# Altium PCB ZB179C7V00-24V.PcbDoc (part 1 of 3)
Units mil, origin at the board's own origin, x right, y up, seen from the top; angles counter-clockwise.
Board outline 6000 x 4000 mil, 2 copper layers (Top Layer, Bottom Layer); 365 components, 297 nets, 1012 pads, 642 vias.
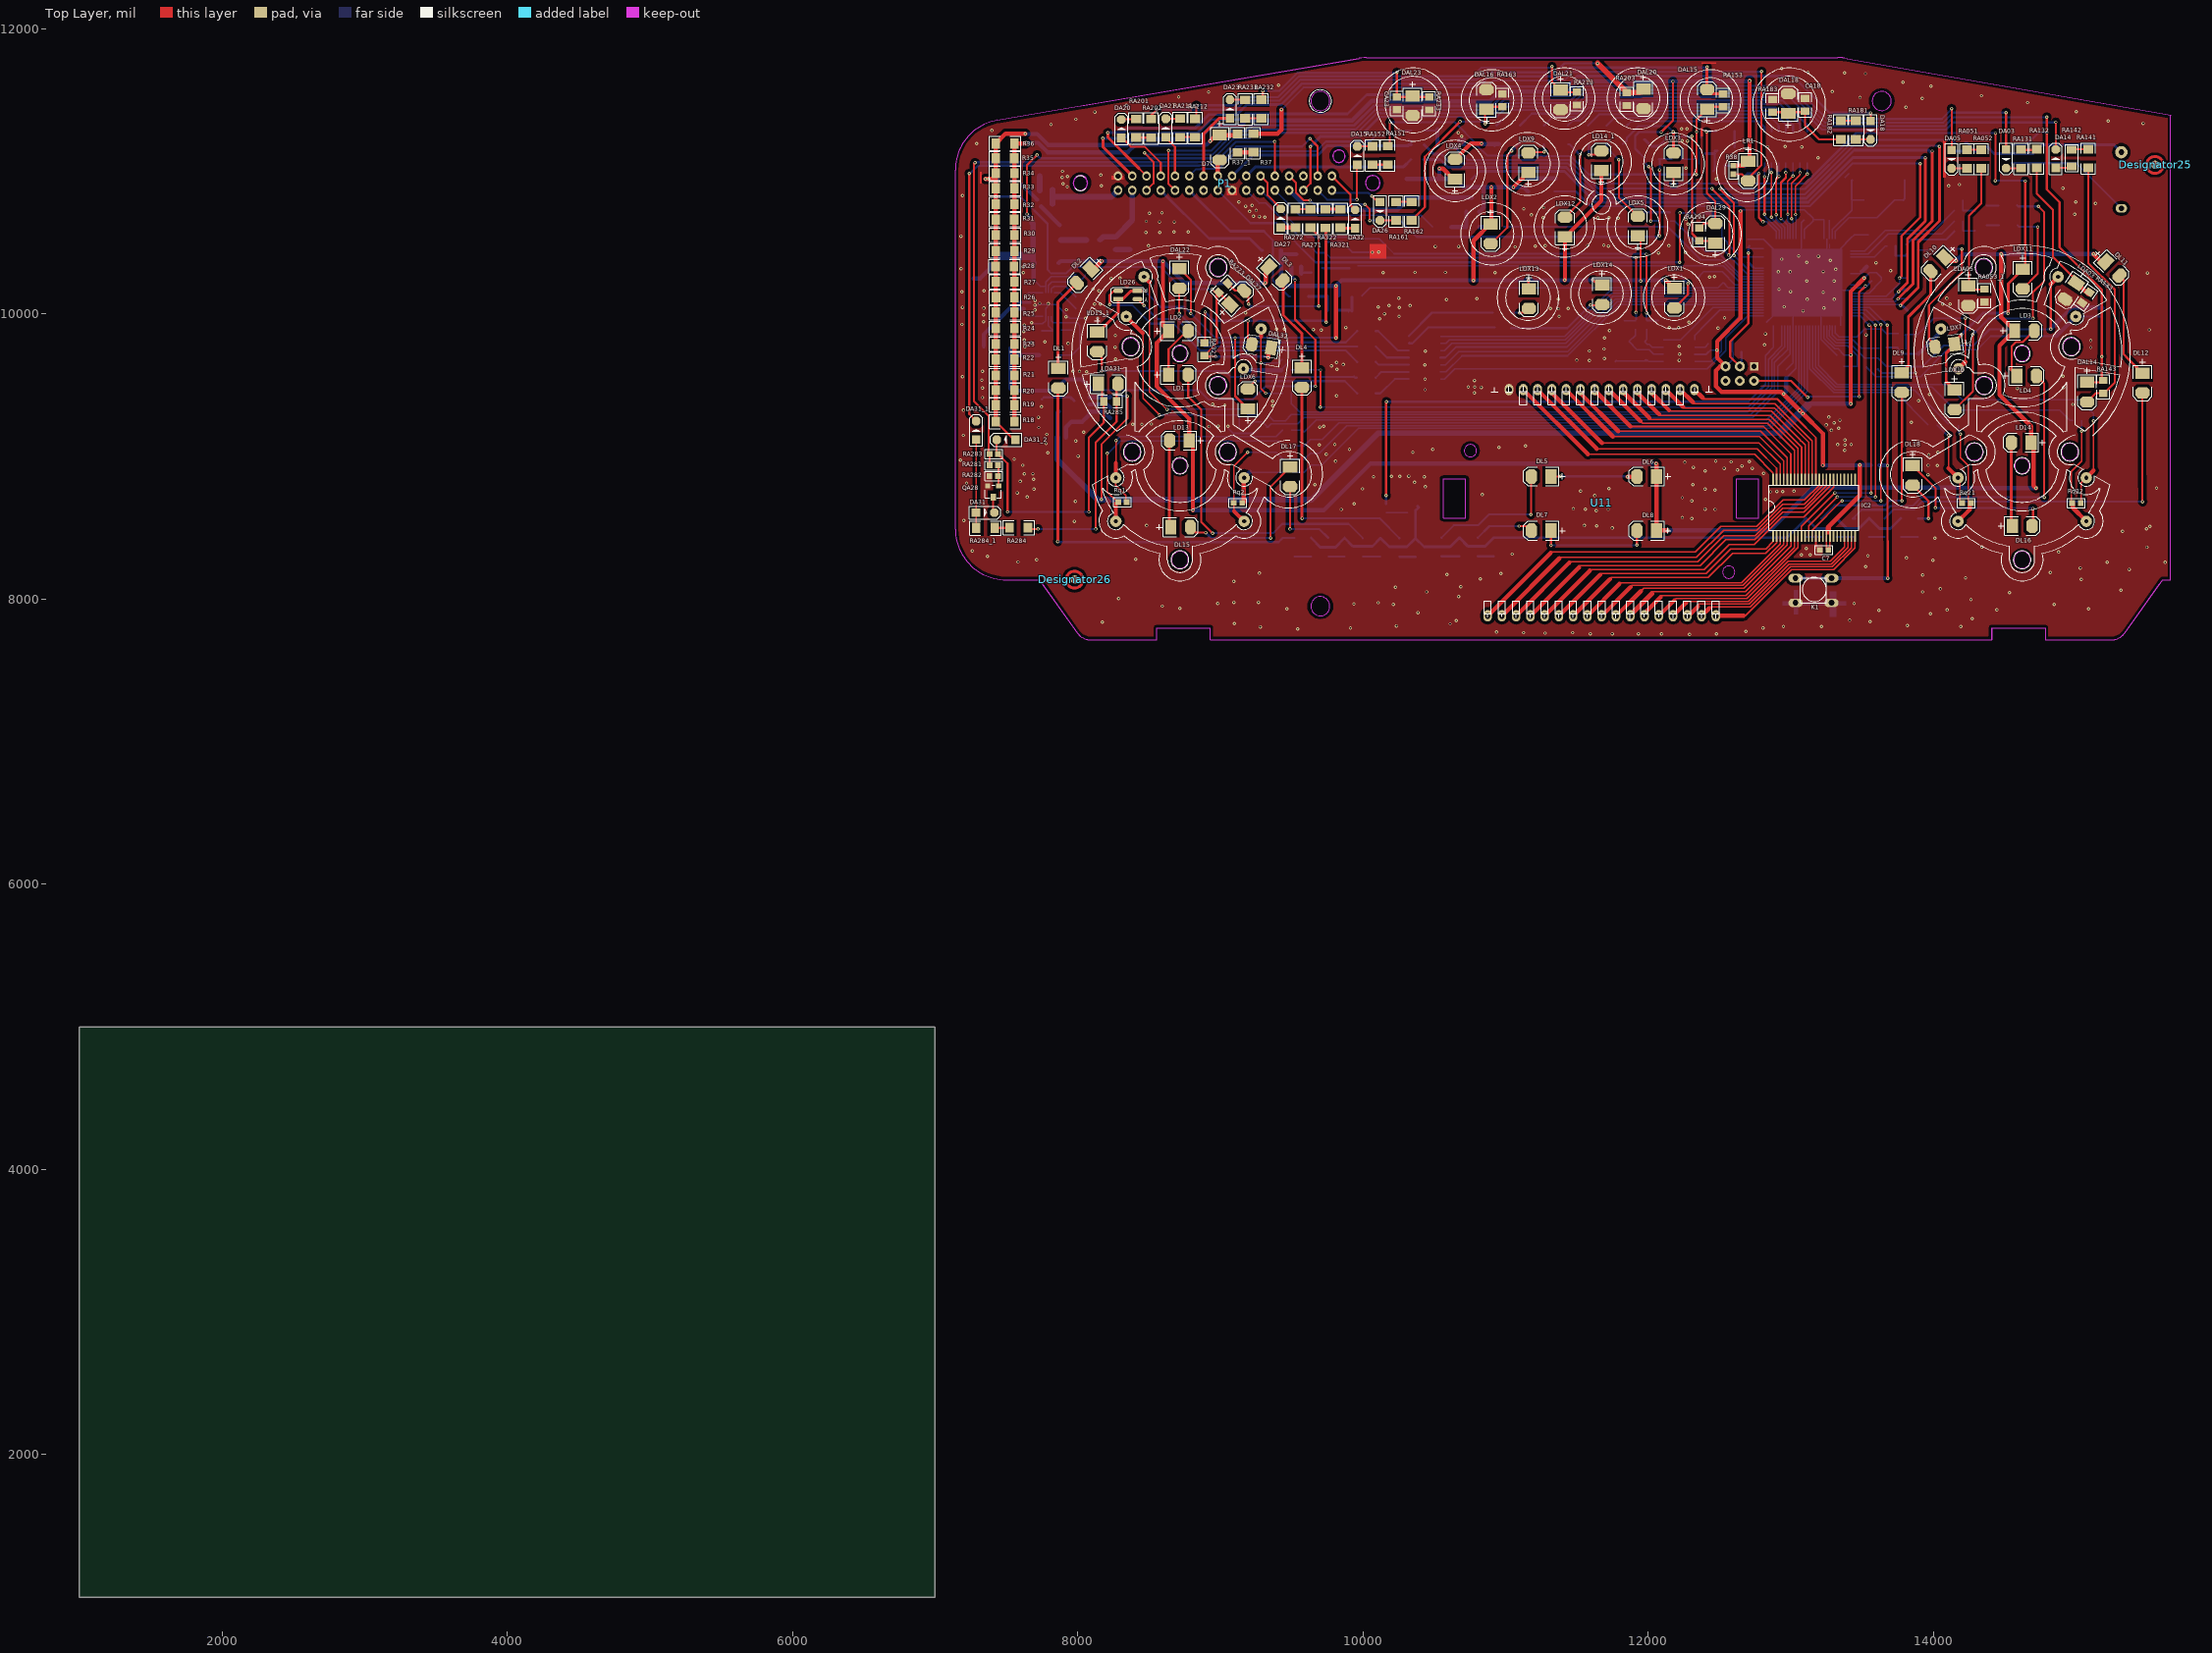
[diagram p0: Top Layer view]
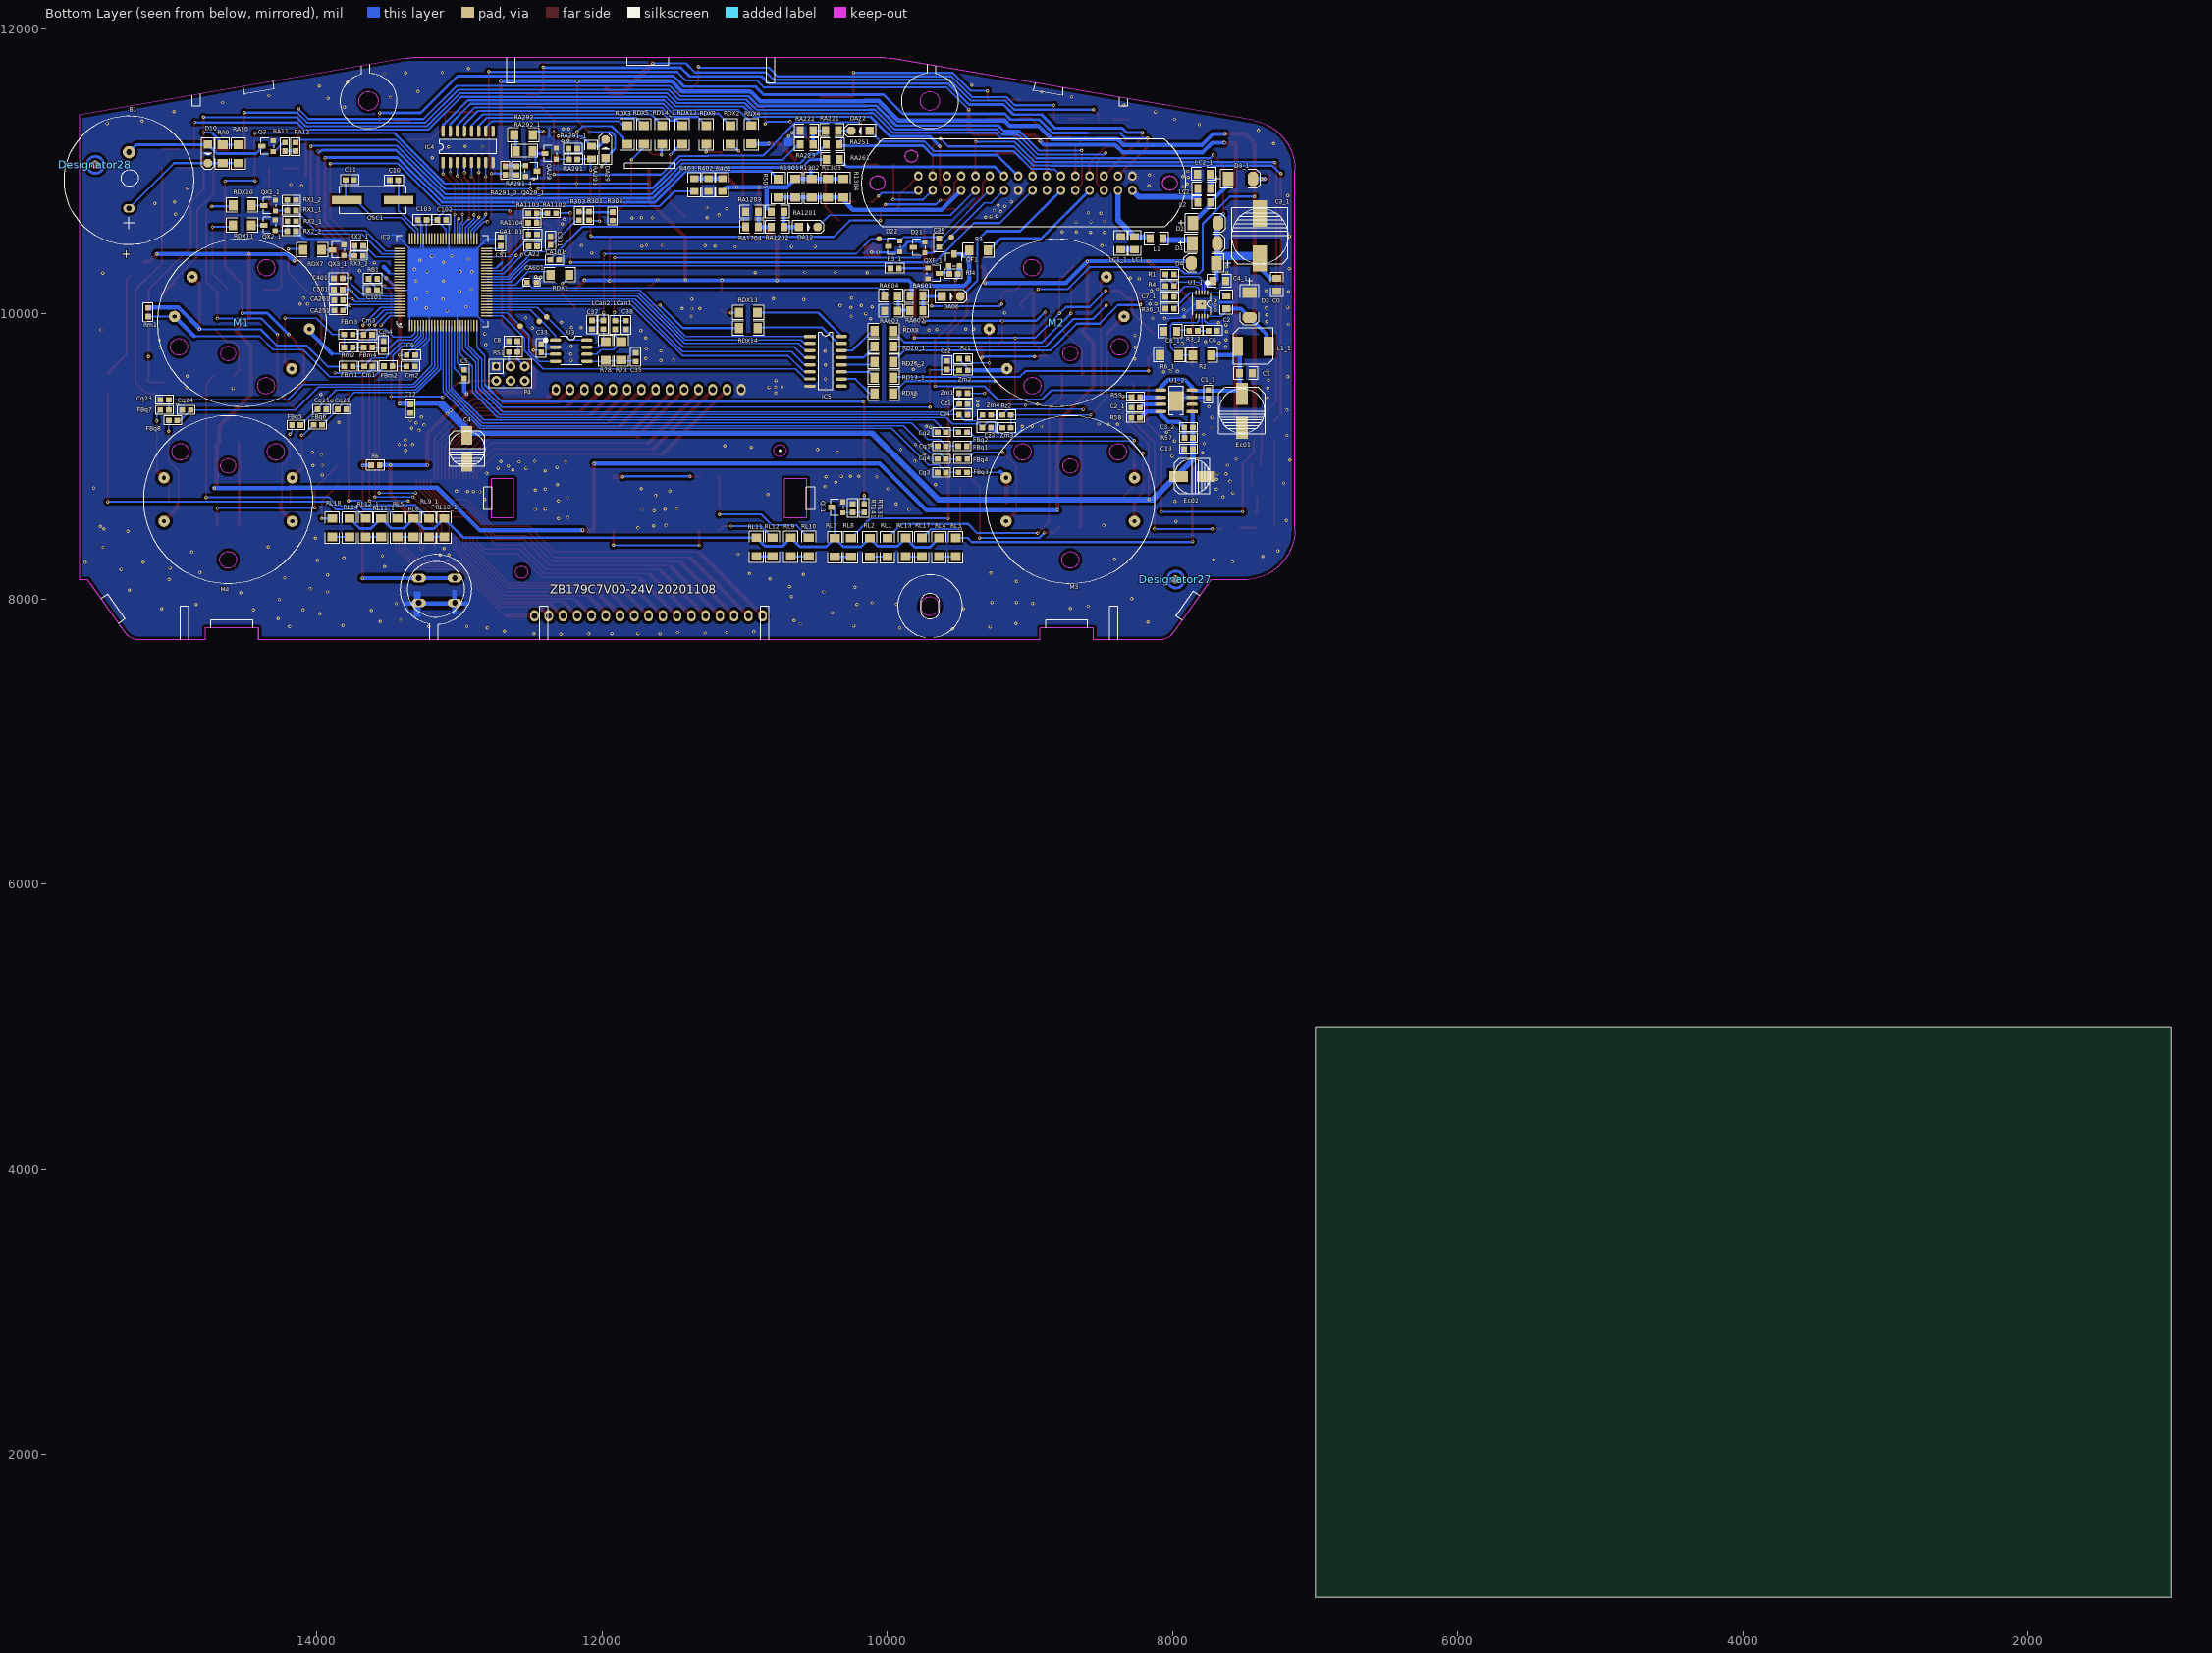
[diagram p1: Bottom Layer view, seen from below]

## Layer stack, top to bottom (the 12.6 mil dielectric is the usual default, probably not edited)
Top Layer: signal copper 1.4
Dielectric: core 12.6, FR-4, Dk 4.8
Bottom Layer: signal copper 1.4

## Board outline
1000,1000 7000,1000 7000,5000 1000,5000

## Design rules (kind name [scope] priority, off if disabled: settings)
Clearance Clearance_1 [All] p1 off: gap=20
Clearance [All] p2: gap=9.5
ComponentClearance [All] p1 off: gap=10 collisioncheckmode=3 verticalgap=10 showdistances=FALSE
FabricationTestPointUsage TestPointUsage [All] p1: valid=0 allowmultiple=FALSE
FabricationTestpoint Testpoint [All] p1: side=3 testpointundercomponent=TRUE minsize=40 maxsize=100 preferedsize=60 minholesize=0 maxholesize=40 preferedholesize=32 testpointgrid=1 allowsidetop=TRUE allowsidebottom=TRUE usegrid=TRUE gridtolerance=0.01
HoleToHoleClearance [All] p1 off: gap=10 allowstackedmicrovias=TRUE
MinimumSolderMaskSliver [All] p1 off: minsoldermaskwidth=10
PlaneConnect [All] p1: planeconnectstyle=Direct reliefexpansion=20 reliefentries=4 reliefconductorwidth=10 reliefairgap=10
PolygonConnect [All] p1: connectstyle=Direct reliefconductorwidth=10 reliefentries=4 polygonreliefangle="90 Angle"
RoutingVias [All] p1: holewidth=11.81 width=23.62 viastyle="Through Hole" minholewidth=11.81 minwidth=23.62 maxholewidth=11.81 maxwidth=23.62
SilkToSilkClearance [All] p1 off: silktosilkclearance=10
SilkscreenOverComponentPads [All] p1 off: minsilkscreentomaskgap=10
SolderMaskExpansion [All] p1: expansion=4
Width [All] p1: maxlimit=100 minlimit=9.8 preferedwidth=10 minimp=50.000000 maximp=50.000000 favimp=50.000000
20 further rules are at their usual default settings.

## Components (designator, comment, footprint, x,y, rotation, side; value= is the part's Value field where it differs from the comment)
B1 "BMT2512H12-04 LF" AZ-2320E-P1 15319,10740 r90 bottom locked
C0 "2.2uF/50V" 0805 7269,10249 r270 bottom
C1 "1uF/50V" 0805 7531,9584 r180 bottom
C1_1 "1uF/50V" 0603 7750,9467 r270 bottom
C2 "0.1uF/16V" 0805 7622,10126 r270 bottom
C2_1 "47nF/50V" 0603 8289,9342 r180 bottom
C3_1 "220/50V" VZH220/50V 7387,10546 r270 bottom
C3_2 "2.2nF" 0603 7858,9205 r0 bottom
C4 "220/16V" VD220/16V 12948,9053 r90 bottom
C4_1 "0.1uF/50V" 0805 7718,10231 r180 bottom
C5 "0.1uF/16V" 0603 12968,9608 r270 bottom
C6 "33pF/16V" 0603 7688,9882 r0 bottom
C7 "0.1uF/16V" 0603 13204,8344 r0 top
C7_1 "0.01uF/16V" 0603 8051,10118 r180 bottom
C8 "0.1uF/16V" 0603 12655,9808 r180 bottom
C8_1 "4700pF/16V" 0805 8062,9878 r180 bottom
C9 "0.1uF/16V" 0603 13311,9711 r0 bottom
C10 "20*" 0603 13430,10937 r0 bottom
C11 "20*" 0603 13800,10940 r180 bottom
C12 "0.1uF/16V" 0603 13346,9305 r90 bottom (schematic designator C5)
C13 "0.1uF/16V" 0603 7919,9051 r180 bottom (schematic designator C5)
C33 "0.1uF/50V" 0603 12427,9729 r90 bottom
C35 "0.1uF/50V" 0603 11765,9666 r90 bottom
C37 "20pF//50V" 0603 12071,9953 r270 bottom
C38 "20pF//50V" 0603 11832,9892 r90 bottom
C39 "20pF//50V" 0603 9638,10468 r90 bottom
C101 "0.1uF/16V" 0603 13639,10168 r180 bottom
C102 "0.1uF/16V" 0603 13096,10660 r0 bottom
C103 "0.1uF/16V" 0603 13291,10659 r180 bottom
C301 "0.01uF/50V" 0603 12362,10544 r270 bottom
C401 "0.01uF/50V" 0603 13821,10249 r0 bottom
C501 "0.01uF/50V" 0603 13821,10170 r0 bottom
CA18 "0.1uF/50V" 0805 13101,11421 r90 top
CA22 "0.01uF/50V" 0603 12516,10474 r180 bottom
CA23 "0.1uF/50V" 0805 10238,11522 r270 top
CA101 "0.01uF/50V" 0603 12363,10379 r180 bottom
CA251 "0.01uF/50V" 0603 13818,10024 r0 bottom
CA261 "0.01uF/50V" 0603 13818,10095 r0 bottom
CA601 "0.01uF/50V" C0603 12462,10220 r0 bottom
CA1101 "0.01uF/50V" 0603 12517,10557 r180 bottom
Cm1 "NC" 0603 13609,9632 r0 bottom
Cm2 "NC" 0603 13372,9632 r180 bottom
Cm3 "NC" 0603 13674,9853 r180 bottom
Cm4 "NC" 0603 13532,9809 r270 bottom
Cq1 "NC" 0603 9649,9073 r180 bottom
Cq2 "NC" 0603 9589,9170 r0 bottom
Cq3 "NC" 0603 9589,8887 r0 bottom
Cq4 "NC" 0603 9649,8981 r180 bottom
Cq21 "NC" 0603 13935,9331 r0 bottom
Cq22 "NC" 0603 13854,9330 r180 bottom
Cq23 "NC" 0603 15039,9398 r0 bottom
Cq24 "NC" 0603 14945,9325 r180 bottom
CS1 "103" 0603 12712,10537 r270 bottom
Cz1 "NC" 0603 9437,9367 r0 bottom
Cz2 "NC" 0603 9582,9609 r90 bottom
Cz3 "NC" 0603 9335,9203 r180 bottom
Cz4 "NC" 0603 9438,9293 r0 bottom
D1 "M7" 7227 7861,10494 r180 bottom
D2 "M7" 7227 7858,10637 r180 bottom
D3 "B360" 7227 7460,10150 r270 bottom
D3_1 "M7" 7227 7611,10947 r180 bottom
D4 "M7" 7227 7692,10356 r0 bottom
D7 "M7" 7227 8997,11254 r270 top
D10 "430" MiniMELF/SOD-80C 14765,11122 r270 bottom
D21 "MMBZ27VCLT1" SOT-23-BEC#1 9818,10466 r90 bottom
D22 "MMBZ27VCLT1" SOT-23-BEC#1 9993,10473 r90 bottom (schematic designator D21)
DA03 "4148" MiniMELF/SOD-80C 14510,11087.5 r270 top
DA05 "4148" MiniMELF/SOD-80C 14129,11085.5 r270 top
DA06 "4148" MiniMELF/SOD-80C 9553,10122 r180 bottom
DA12 "4148" MiniMELF/SOD-80C 10555,10609 r180 bottom
DA14 "4148" MiniMELF/SOD-80C 14859,11089 r90 top
DA15 "4148" MiniMELF/SOD-80C 9961,11110 r90 top
DA18 "4148" MiniMELF/SOD-80C 13561,11288 r270 top
DA20 "4148" MiniMELF/SOD-80C 8306,11299 r90 top
DA21 "4148" MiniMELF/SOD-80C 8618,11304 r90 top
DA22 "4148" MiniMELF/SOD-80C 10189,11283 r0 bottom
DA23 "4148" MiniMELF/SOD-80C 9067,11437 r90 top
DA26 "4148" MiniMELF/SOD-80C 10120,10720 r270 top
DA27 "4148" MiniMELF/SOD-80C 9424,10671 r90 top
DA29 "4148" MiniMELF/SOD-80C 11976,11157 r90 bottom
DA31 "4148" MiniMELF/SOD-80C 7351,8605 r0 top
DA31_1 "4148" MiniMELF/SOD-80C 7289,9183 r90 top
DA31_2 "4148" MiniMELF/SOD-80C 7498,9117 r180 top
DA32 "4148" MiniMELF/SOD-80C 9945,10665 r90 top
DAL14 "R" LED3528#1 15078,9520 r270 top
DAL15 "B" LED3528#2 12414,11436 r90 top
DAL16 "G" LED3528#2 10867,11434 r90 top
DAL18 "G" LED3528#1 12983,11406 r90 top
DAL20 "Y" LED3528#2 11967,11578 r270 top
DAL21 "G" LED3528#2 11386,11569 r270 top
DAL22 "Y" LED3528#1 8713,10318 r270 top
DAL23 "G" LED3528#2 10348,11530 r270 top
DAL27 "R" LED3528#2 9069,10065 r45 top
DAL29 "Y" LED3528#2 12472,10496 r90 top
DAL32 "R" LED3528#1 9357,9762 r170 top
Designator25 "Comment" MARK 15555,11045 r90 top
Designator26 "Comment" MARK 7979,8136 r90 top
Designator27 "Comment" MARK 7979,8136 r270 bottom
Designator28 "Comment" MARK 15555,11045 r270 bottom
DL1 "W" LED3528#2 7865,9617 r270 top
DL2 "W" LED3528#2 8093,10315 r225 top
DL3 "W" LED3528#2 9339,10330 r315 top
DL4 "W" LED3528#2 9573,9623 r270 top
DL5 "W" LED3528#2 11320,8860 r180 top
DL6 "W" LED3528#2 12060,8860 r180 top
DL7 "W" LED3528#2 11320,8480 r180 top
DL8 "W" LED3528#2 12060,8480 r180 top
DL9 "W" LED3528#1 13779,9586 r270 top
DL10 "W" LED3528#1 14079,10397 r225 top
DL11 "W" LED3528#1 15209,10366 r315 top
DL12 "W" LED3528#1 15467,9584 r270 top
DL15 "W" LED3528#1 8653,8504 r0 top
DL16 "W" LED3528#1 14555,8513 r0 top
DL17 "W" LED3528#1 9490,8926 r270 top
DL18 "W" LED3528#1 13855,8936 r270 top
Ec01 "100uF/25V" 4E220/16H 7514,9320 r90 bottom
Ec02 "220/16V" VD220/16V 7862,8860 r0 bottom
FBm1 "600" 0603 13749,9631 r0 bottom
FBm2 "600" 0603 13470,9633 r0 bottom
FBm3 "600" 0603 13810,9855 r180 bottom
FBm4 "600" 0603 13672,9765 r180 bottom
FBq1 "600" 0603 9503,9072 r180 bottom
FBq2 "600" 0603 9502,9171 r180 bottom
FBq3 "600" 0603 9442,8888 r0 bottom
FBq4 "600" 0603 9440,8981 r0 bottom
FBq5 "600" 0603 14116,9220 r0 bottom
FBq6 "600" 0603 13964,9222 r0 bottom
FBq7 "600" 0603 15099,9325 r180 bottom
FBq8 "600" 0603 15039,9253 r180 bottom
IC2 "HT1621B" SSO-48 12846,8481 r90 top locked
IC3 "MC9S12HY48MLL" TQFP-100-0.5 13115,10223 r180 bottom
IC4 "ULQ2003" SO-16#1 13116,11061 r90 bottom
IC5 "ULQ2003" SO-16#2 10543,9843 r180 bottom
K1 "KEY" K1 13160,8060 r0 top locked
L1 "600" 0805 8068,10528 r0 bottom
L1_1 "10uH" SPM6530T-100M 7435,9773 r180 bottom
L2 "600" 0805 7734,10781 r0 bottom
LC1 "0.1uF/50V" 0805 8267,10451 r90 bottom
LC1_1 "0.1uF/50V" 0805 8364,10541 r270 bottom
LC2 "0.1uF/50V" 0805 7824,10879 r180 bottom
LC2_1 "0.1uF/50V" 0805 7736,10980 r0 bottom
LCan1 "30Ω" 0603 11910,9892 r90 bottom
LCan2 "30Ω" 0603 11992,9893 r90 bottom
LD1 "R" LED3528#2 8637,9573 r0 top
LD2 "R" LED3528#2 8637,9879 r0 top
LD3 "R" LED3528#2 14570,9882 r0 top
LD4 "R" LED3528#2 14584,9565 r0 top
LD13 "R" LED3528#1 8781,9112 r180 top
LD13_1 "R" LED3528#2 8137,9873 r270 top
LD14 "R" LED3528#1 14685,9097 r180 top
LD14_1 "G" LED3528#1 11672,11005 r90 top
LD26 "Y/G" 67-22 8419,10104 r180 top
LDA03 "G" LED3528#1 15003,10216 r235 top
LDA05 "Y" LED3528#1 14245,10197 r270 top
LDA31 "R" LED3528#2 8145,9508 r0 top
LDX1 "R" LED3528#2 12184,10178 r270 top
LDX2 "Y" LED3528#1 10896,10631 r270 top
LDX3 "Y" LED3528#2 12179,10991 r90 top
LDX4 "Y" LED3528#1 10646,10945 r90 top
LDX5 "Y" LED3528#1 11928,10546 r90 top
LDX6 "R" LED3528#1 9194,9334 r90 top
LDX7 "R" LED3528#1 14148,9788 r188 top
LDX9 "Y" LED3528#1 11161,10992 r90 top
LDX10 "R" LED3528#1 14149,9466 r270 top
LDX11 "Y" LED3528#1 14627,10314 r270 top
LDX12 "R" LED3528#1 11417,10539 r90 top
LDX13 "Y" LED3528#1 11164,10175 r270 top
LDX14 "R" LED3528#1 11678,10202 r270 top
LR1 "R" LED3528#2 12702,11072 r270 top
M1 "CS" M 14622.69,9721.27 r204 bottom locked
M2 "ZS" M 8717.17,9721.27 r156 bottom locked
M3 "QY1" M 8717.14,8934.7 r0 bottom locked
M4 "QY2" M 14622.66,8934.7 r0 bottom locked
OSC1 "8M/20P" HC-49S 13609,10798 r0 bottom
P1 "Port16*2" AMP-32-B 9832.79,10729.69 r180 top locked
P4 "Port3*2" SIP-6 12743,9530 r180 bottom
Q3 "MMBT5551" SOT-23-BEC#1 14387,11175 r90 bottom
Q11 "5551" SOT-23-BEC#1 10392,8643 r90 bottom
QA28 "5551" SOT-23-BEC#1 7408,8714 r180 top
QA29 "5551" SOT-23-BEC#2 12402,11123 r90 bottom
QA29_1 "5551" SOT-23-BEC#1 12457,11002 r270 bottom
QF1 "AO3401" SOT-23-GSD 9538,10375 r180 bottom
QX1_1 "5551" SOT-23-BEC#1 14372,10759 r90 bottom
QX2_1 "5551" SOT-23-BEC#1 14373,10622 r90 bottom
QX3_1 "5551" SOT-23-BEC#1 13891,10448 r90 bottom
QXF_1 "5551" SOT-23-BEC#1 9635,10284 r270 bottom
R1 "332K" 0603 8051,10276 r180 bottom
R2 "139K" 1206#1 7858,9710 r180 bottom
R3 "100" 1206#1 9426,10446 r180 bottom
R3_1 "1K" 0603 9918,10319 r0 bottom
R3_2 "20K" 0603 7884,9882 r180 bottom
R4 "23.3K" 0603 8051,10196 r180 bottom
R6 "10K" 0603 13620,8938 r180 bottom
R6_1 "10K" 1206#1 8088,9711 r180 bottom
R18 "2.4KΩ" 1206#1 7556,9245 r180 top
R19 "2.4KΩ" 1206#1 7556,9360 r180 top
R20 "2.4KΩ" 1206#1 7556,9464 r180 top
R21 "2.4KΩ" 1206#1 7556,9568 r180 top
R22 "2.4KΩ" 1206#1 7556,9680 r180 top
R23 "2.4KΩ" 1206#1 7556,9789 r180 top
R24 "2.4KΩ" 1206#1 7556,9899 r180 top
R25 "2.4KΩ" 1206#1 7556,10010 r180 top
R26 "2.4KΩ" 1206#1 7557,10117 r180 top
R27 "2.4KΩ" 1206#1 7556,10225 r180 top
R28 "2.4KΩ" 1206#1 7554,10331 r180 top
R29 "2.4KΩ" 1206#1 7556,10441 r180 top
R30 "2.4KΩ" 1206#1 7556,10552 r180 top
R31 "2.4KΩ" 1206#1 7555,10661 r180 top
R32 "2.4KΩ" 1206#1 7556,10770 r180 top
R33 "2.4KΩ" 1206#1 7556,10881 r180 top
R34 "2.4KΩ" 1206#1 7556,10986 r180 top
R35 "2.4KΩ" 1206#1 7555,11091 r180 top
R36 "2.4KΩ" 1206#1 7556,11195 r180 top
R36_1 "237KΩ" 0603 8051,10036 r180 bottom
R37 "1K" 1206#1 9233,11134 r90 top
R37_1 "1K" 1206#1 9122,11262 r270 top
R38 "1KΩ" 0603 12599,10979 r90 top
R57 "300K" 0603 7917,9130 r180 bottom
R58 "100K" 0603 8230,9270 r0 bottom
R59 "100K" 0603 8228,9418 r0 bottom
R73 "60.4Ω" 1206#1 11866,9806 r270 bottom
R78 "60.4Ω" 1206#1 11975,9675 r90 bottom
R301 "100KΩ" 0603 12092,10658 r90 bottom
R302 "51KΩ" 0603 11926,10714 r270 bottom
R303 "51KΩ" 0603 12163,10658 r90 bottom
R401 "56K 1%" 0805 11157,10949 r270 bottom
R402 "20k 1%" 0805 11254,10949 r270 bottom
R403 "10KΩ" 0805 11354,10859 r90 bottom
R505 "10KΩ" 1206#1 10764,10945 r270 bottom
R1301 "1.5K 1%" 1206#1 10647,10816.39 r90 bottom
R1302 "1.5K 1%" 1206#1 10531,10816.39 r90 bottom
R1303 "NC" 1206#1 10417,10816.39 r90 bottom
R1304 "1.5K 1%" 1206#1 10308,10816.39 r90 bottom
RA9 "330Ω" 1206#1 14662,11056.5 r90 bottom
RA10 "330Ω" 1206#1 14549,11056.5 r90 bottom
RA11 "4.7KΩ" 0603 14224,11201 r270 bottom
RA12 "4.7KΩ" 0603 14151,11141 r90 bottom
RA051 "1K" 1206#1 14236,11021 r90 top
RA052 "1K" 1206#1 14337,11151 r270 top
RA053_1 "1K" 0805 14358,10173 r270 top
RA131 "1K" 1206#1 14616,11023 r90 top
RA132 "1K" 1206#1 14725,11154.5 r270 top
RA133 "1K" 0805 15095,10151 r235 top
RA141 "1K" 1206#1 15086,11154.5 r270 top
RA142 "2.2k" 1206#2 14970,11092 r90 top
RA143 "1KΩ" 0805 15191,9443 r90 top
RA151 "1K" 1206#1 10174,11047 r90 top
RA152 "1K" 1206#1 10069,11176 r270 top
RA153 "1KΩ" 0805 12525,11453 r90 top
RA161 "1K" 1206#1 10232,10785.5 r270 top
RA162 "1K" 1206#1 10342,10655.5 r90 top
RA163 "1KΩ" 0805 10978,11542 r270 top
RA181 "1K" 1206#1 13457,11224 r90 top
RA182 "1K" 1206#1 13351,11354 r270 top
RA183 "1K" 0805 12873,11505 r270 top
RA201 "1K" 1206#1 8410,11367 r270 top
RA202 "1K" 1206#1 8515,11236 r90 top
RA203 "1KΩ" 0805 11851,11552 r270 top
RA211 "1K" 1206#1 8719,11370 r270 top
RA212 "1K" 1206#1 8824,11239 r90 top
RA213 "1KΩ" 0805 11501,11555 r270 top
RA221 "100KΩ" 0805 10434,11286 r180 bottom
RA222 "51KΩ" 0805 10611,11285 r180 bottom
RA223 "51KΩ" 0805 10521,11187 r0 bottom
RA231 "1K" 1206#1 9175,11501 r270 top
RA232 "1K" 1206#1 9288,11372 r90 top
RA233 "1K" 0805 10466,11431 r90 top
RA251 "10KΩ" 0805 10430,11187 r180 bottom
RA261 "10KΩ" 0805 10427,11083 r180 bottom
RA271 "1K" 1206#1 9632,10604 r90 top
RA272 "1K" 1206#1 9527,10734 r270 top
RA273 "1KΩ" 0805 8990,10150 r45 top
RA281 "20KΩ" 0603 7382,8937 r0 top
RA282 "2.4KΩ" 0603 7381,8863 r0 top
RA283 "4.3KΩ" 0603 7382,9017 r0 top
RA284 "1K" 1206#1 7522,8500 r0 top
RA284_1 "1K" 1206#1 7419,8499 r180 top
RA285 "430Ω" 0805 8183,9386 r0 top
RA291 "20KΩ" 0603 12174,11082 r0 bottom
RA291_1 "2.4KΩ" 0603 12175,11159 r0 bottom
RA291_3 "20KΩ" 0603 12679,10975 r90 bottom
RA291_4 "2.4KΩ" 0603 12601,10974 r90 bottom
RA292 "1K" 1206#1 12487,11255 r0 bottom
RA292_1 "2.2KΩ" 1206#2 12547,11142 r180 bottom
RA293 "4.3KΩ" 0805 12075,11086 r90 bottom
RA294 "430Ω" 0805 12359,10512 r90 top
RA321 "1K" 1206#1 9843,10734 r270 top
RA322 "1K" 1206#1 9738,10733 r270 top
RA323 "1KΩ" 0805 8888,9797 r270 top
RA601 "10KΩ" 0805 9841,10125 r180 bottom
RA602 "100KΩ" 0805 9752,10022 r0 bottom
RA603 "51KΩ" 0805 9929,10020 r0 bottom
RA604 "10KΩ" 0805 9929,10126 r0 bottom
RA1102 "100KΩ" 0603 12384,10705 r180 bottom
RA1103 "51KΩ" 0603 12518,10705 r180 bottom
RA1104 "51KΩ" 0603 12458,10638 r0 bottom
RA1201 "10KΩ" 0805 10725,10715 r0 bottom
RA1202 "100KΩ" 0805 10815,10610 r180 bottom
RA1203 "51KΩ" 0805 10994,10715 r180 bottom
RA1204 "51KΩ" 0805 10904,10611 r0 bottom
RB1 "10KΩ" 0603 13577,10247 r0 bottom
RD13_1 "820Ω" 1206#1 10090,9553 r180 bottom
RD14_1 "820Ω" 1206#1 11578,11320 r270 bottom
RD26_1 "820Ω" 1206#1 9960,9771 r0 bottom
RD26_2 "620Ω" 1206#1 10090,9663 r180 bottom
RDX1 "820" 1206#1 12232,10273 r0 bottom
RDX2 "820Ω" 1206#1 11100,11190 r90 bottom
RDX3 "820Ω" 1206#1 11824,11190 r90 bottom
RDX4 "820Ω" 1206#1 10954,11322 r270 bottom
RDX5 "820Ω" 1206#1 11708,11320 r270 bottom
RDX6 "820Ω" 1206#1 10090,9442 r180 bottom
RDX7 "820Ω" 1206#1 13968,10450 r0 bottom
RDX8 "820" 1206#1 9960,9880 r0 bottom
RDX9 "820Ω" 1206#1 11269,11190 r90 bottom
RDX10 "820Ω" 1206#1 14588,10761 r180 bottom
RDX11 "820Ω" 1206#1 14460,10622 r0 bottom
RDX12 "820Ω" 1206#1 11437,11320 r270 bottom
RDX13 "820Ω" 1206#1 10911,10008 r0 bottom
RDX14 "820Ω" 1206#1 10910,9900 r0 bottom
Rf4 "20K" 0603 9566,10281 r180 bottom
RL1 "1K" 1206#1 10000,8297 r90 bottom
RL2 "1K" 1206#1 10124,8427 r270 bottom
RL3 "1K" 1206#1 9521,8298 r90 bottom
RL4 "1K" 1206#1 9638,8428 r270 bottom
RL5 "1K" 1206#1 13436,8435 r90 bottom
RL6 "1K" 1206#1 13323,8565 r270 bottom
RL7 "1K" 1206#1 10369,8426 r270 bottom
RL8 "1K" 1206#1 10256,8297 r90 bottom
RL9 "1K" 1206#1 10677,8430 r270 bottom
RL9_1 "1K" 1206#1 13215,8435 r90 bottom
RL10 "1K" 1206#1 10551,8430 r270 bottom
RL10_1 "1K" 1206#1 13108,8565 r270 bottom
RL11 "1K" 1206#1 10918,8430 r270 bottom
RL11_1 "1K" 1206#1 13550,8565 r270 bottom
RL12 "1K" 1206#1 10806,8430 r270 bottom
RL12_1 "1K" 1206#1 13658,8565 r270 bottom
RL13 "1K" 1206#1 9872,8428 r270 bottom
RL14 "1K" 1206#1 13771,8565 r270 bottom
RL17 "1K" 1206#1 9758,8298 r90 bottom
RL18 "1K" 1206#1 13892,8435 r90 bottom
Rm1 "NC" 0603 15184,9981 r90 bottom
Rm2 "NC" 0603 13809,9765 r180 bottom
Rq1 "NC" 0603 8344,8680 r180 top
Rq2 "NC" 0603 9154,8675 r180 top
Rq21 "NC" 0603 14203,8672 r0 top
Rq22 "NC" 0603 15033,8673 r180 top
RS1 "10K" 0603 12655,9732 r180 bottom
RT131 "1KΩ" 0603 10163,8666.5 r270 bottom
RT141 "10KΩ" 0603 10243,8606.5 r90 bottom
RX1_1 "1KΩ" 0603 14148,10725 r0 bottom
RX1_2 "10KΩ" 0603 14208,10798 r180 bottom
RX2_1 "1KΩ" 0603 14147,10651 r0 bottom
RX2_2 "10KΩ" 0603 14208,10580 r180 bottom
RX3_1 "1KΩ" 0603 13676,10476 r0 bottom
RX3_2 "10KΩ" 0603 13737,10406 r180 bottom
Rz1 "NC" 0603 9496,9684 r180 bottom
Rz2 "NC" 0603 9134,9291 r0 bottom
U1_1 "TPS54260" MSOP 7756,10149 r0 bottom
U1_2 "MPQ2029" SOIC8 7864,9315 r0 bottom
U3 "TJA1040" SO-8 12327,9817 r180 bottom
U11 "Ul1" LCD 10753.39,9040.16 r0 top locked
Zm1 "600" 0603 9498,9444 r180 bottom
Zm2 "600" 0603 9496.4,9604 r180 bottom
Zm3 "600" 0603 9134,9202 r0 bottom
Zm4 "600" 0603 9273,9291 r0 bottom

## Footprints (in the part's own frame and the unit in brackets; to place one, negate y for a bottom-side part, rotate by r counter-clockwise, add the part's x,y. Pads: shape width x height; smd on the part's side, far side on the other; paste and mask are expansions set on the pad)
4E220/16H [mil]
  rect 155x85 smd: 1(120,0) 2(-120,0)
  silkscreen extent -164,-164 164,165
67-22 [mm]
  oct 1.8x0.75 smd: 1(0,0) 4(3.4,-1.45)
  rect 1.8x0.75 smd: 2(0,-1.45) 3(3.4,0)
  silkscreen extent -1.1,-2.09 4.65,0.64
0603 [mil]
  rect 40x40 smd: 1(0,0) 2(60,0)
  silkscreen extent -32,-32 92,32
0805 [mil]
  rect 50x60 smd: 1(0,0) 2(90,0)
  silkscreen extent -40,-45 130,45
1206#1 [mil]
  rect 60x70 smd: 1(0,0) 2(130,0)
  silkscreen extent -45,-50 175,50
1206#2 [mil]
  rect 55.12x70 smd: 1(-59.06,0) 2(59.06,0)
  silkscreen extent -95,-45 95,45
7227 [mil]
  rect 75x100 smd: 1(0,0)
  oct 75x100 smd: 2(175,0)
  silkscreen extent -100,-65 228,65
AMP-32-B [mil]
  oval 59.05x65 hole 35.43: 1(1550,-137) 2(1450,-137) 3(1350,-137) 4(1250,-137) 5(1150,-137) 6(1050,-137) 7(950,-137) 8(850,-137) 9(750,-137) 10(650,-137) 11(550,-137) 12(450,-137) 13(350,-137) 14(250,-137) 15(150,-137) 16(50,-137) 17(1550,-237) 18(1450,-237) 19(1350,-237) 20(1250,-237) 21(1150,-237) 22(1050,-237) 23(950,-237) 24(850,-237) 25(750,-237) 26(650,-237) 27(550,-237) 28(450,-237) 29(350,-237) 30(250,-237) 31(150,-237) 32(50,-237)
  Keep-Out Layer lines w5: 1862.99,-187 ccw(c1813.78,-187) 1764.57,-187 ccw(c1813.78,-187) 1862.99,-187
AZ-2320E-P1 [mm]
  oval 1.524x2.032 hole 1: 1(0.002,-0.011)
  round 2.2 hole 1: 2(10.002,-0.011)
  silkscreen extent -6.5,-11.51 16.5,11.49
C0603 [mil]
  rect 37x37 smd: 1(0,0) 2(64.96,0)
  silkscreen extent -26,-26 91,26
HC-49S [mm]
  rect 5.3x1.524 smd: 1(-4.6,0) 2(4.6,0)
  silkscreen extent -5.97,-2.35 5.95,2.41
K1 [mil]
  oval 100x60 hole 40: 1(-125.98,-86.61) 1(125.98,-86.61) 2(-125.98,86.61) 2(125.98,86.61)
  silkscreen extent -91,-87 91,87
LCD [mil]
  oval 60x80 hole 39.37: 1(121.39,-1158.34) 2(221.39,-1158.34) 3(321.39,-1158.34) 4(421.39,-1158.34) 5(521.39,-1158.34) 6(621.39,-1158.34) 7(721.39,-1158.34) 8(821.39,-1158.34) 9(921.39,-1158.34) 10(1021.39,-1158.34) 11(1121.39,-1158.34) 12(1221.39,-1158.34) 13(1321.39,-1158.34) 14(1421.39,-1158.34) 15(1521.39,-1158.34) 16(1621.39,-1158.34) 17(1721.39,-1158.34) 18(1571.38,428.27) 19(1471.4,428.28) 20(1371.4,428.28) 21(1271.4,428.28) 22(1171.4,428.28) 23(1071.4,428.28) 24(971.4,428.28) 25(871.4,428.28) 26(771.4,428.28) 27(671.4,428.28) 28(571.4,428.28) 29(471.4,428.28) 30(371.4,428.28) 31(271.38,428.27)
  silkscreen extent 96,-1187 1746,456
LED3528#1 [mm]
  rect 2x2.6 smd: 1(0,0)
  oct 2x2.6 smd: 2(3.5,0)
  silkscreen extent -2.54,-1.68 4.87,1.68
LED3528#2 [mm]
  rect 2x2.6 smd: 1(0.01,0.009)
  oct 2x2.6 smd: 2(3.51,0.009)
  silkscreen extent -2.53,-1.67 4.88,1.69
M [mil]
  round 80 hole 30: 1(-449.59,389.59) 2(-449.6,84.47) 3(450.01,84.47) 4(450.01,389.59)
  Keep-Out Layer circle w4: c0.21,0.81 r52
  Keep-Out Layer circle w4: c0.21,660.26 r59.05
  Keep-Out Layer circle w4: c334.85,-97.62 r59.05
  Keep-Out Layer circle w4: c-334.44,-97.62 r59.05
  silkscreen extent -590,-353 591,828
MARK [mm]
  round 1.5 smd: 0(0,0)
  Top Layer circle w0.5: c-0.012,0.014 r1.5
MiniMELF/SOD-80C [mil]
  rect 60x60 smd: 1(-65,0)
  oct 60x60 smd: 2(65,0)
  silkscreen extent -110,-45 110,45
MSOP [mm]
  oval 0.25x0.85 smd: 1(0,0) 2(0.5,0) 3(1,0) 4(1.5,0) 5(2,0) 6(2,4.2) 7(1.5,4.2) 8(1,4.2) 9(0.5,4.2) 10(0,4.2)
  rect 1.88x1.57 smd: 11(1.143,2.159)
  silkscreen extent -0.64,-2.03 2.67,3.94
SIP-6 [mil]
  round 70 hole 35.43: 1(0,0) 3(100,0) 4(99.36,101.4) 5(200,0) 6(199.36,101.4)
  rect 60x60 hole 35.43: 2(-0.64,101.4)
  silkscreen extent -51,-50 250,151
SO-8 [mil]
  oval 80x24 smd: 1(0,0) 2(0,-50) 3(0,-100) 4(0,-150) 5(220,-150) 6(220,-100) 7(220,-50) 8(220,0)
  silkscreen extent -80,-175 185,25
SO-16#1 [mil]
  rect 80x24 smd: 1(0,0)
  oval 80x24 smd: 2(0,-50) 3(0,-100) 4(0,-150) 5(0,-200) 6(0,-250) 7(0,-300) 8(0,-350) 9(220,-350) 10(220,-300) 11(220,-250) 12(220,-200) 13(220,-150) 14(220,-100) 15(220,-50) 16(220,0)
  silkscreen extent 60,-375 160,25
SO-16#2 [mil]
  rect 80x24 smd: 1(0,0)
  oval 80x24 smd: 2(0,-50) 3(0,-100) 4(0,-150) 5(0,-200) 6(0,-250) 9(220,-350) 10(220,-300) 11(220,-250) 12(220,-200) 13(220,-150) 14(220,-100) 15(220,-50) 16(220,0)
  oval 80x20 smd: 7(0,-300) 8(0,-350)
  silkscreen extent 60,-375 160,25
SOIC8 [mil]
  rect 103.15x138.19 smd: 0(110,-75)
  rect 78.74x24 smd: 1(0,0)
  oval 78.74x24 smd: 2(0,-50) 3(0,-100) 4(0,-150) 5(220,-150) 6(220,-100) 7(220,-50) 8(219,0)
  silkscreen extent 60,-175 160,25
SOT-23-BEC#1 [mil]
  rect 36x36 smd: B(-38,-80.38) E(38,-80.38)
  rect 36x50 smd: C(0,-0.38)
  silkscreen extent -57,-85 57,5
SOT-23-BEC#2 [mil]
  rect 36x36 smd: B(-38,-80) E(38,-80)
  rect 36x50 smd: C(0,0)
  silkscreen extent -57,-85 57,5
SOT-23-GSD [mil]
  rect 36x50 smd: D(5,44.62)
  rect 36x36 smd: G(-33,-35.38) S(43,-35.38)
  silkscreen extent -52,-40 62,50
SPM6530T-100M [mm]
  rect 1.85x3.4 smd: 1(-2.775,0) 2(2.775,0)
  silkscreen extent -3.55,-3.25 3.55,3.25
SSO-48 [mil]
  rect 80x12 smd: 1(-40.01,-29.97) 2(-40.01,-54.97) 3(-40.01,-79.97) 4(-40.01,-104.97) 5(-40.01,-129.97) 6(-40.01,-154.97) 7(-40.01,-179.97) 8(-40.01,-204.97) 9(-40.01,-229.97) 10(-40.01,-254.97) 11(-40.01,-279.97) 12(-40.01,-304.97) 13(-40.01,-329.97) 14(-40.01,-354.97) 15(-40.01,-379.97) 16(-40.01,-404.97) 17(-40.01,-429.97) 18(-40.01,-454.97) 19(-40.01,-479.97) 20(-40.01,-504.97) 21(-40.01,-529.97) 22(-40.01,-554.97) 23(-40.01,-579.97) 24(-40.01,-604.97) 25(359.99,-604.97) 26(359.99,-579.97) 27(359.99,-554.97) 28(359.99,-529.97) 29(359.99,-504.97) 30(359.99,-479.97) 31(359.99,-454.97) 32(359.99,-429.97) 33(359.99,-404.97) 34(359.99,-379.97) 35(359.99,-354.97) 36(359.99,-329.97) 37(359.99,-304.97) 38(359.99,-279.97) 39(359.99,-254.97) 40(359.99,-229.97) 41(359.99,-204.97) 42(359.99,-179.97) 43(359.99,-154.97) 44(359.99,-129.97) 45(359.99,-104.97) 46(359.99,-79.97) 47(359.99,-54.97) 48(359.99,-29.97)
  silkscreen extent 1,-632 316,-2
TQFP-100-0.5 [mm]
  rect 0.25x2 smd: 1(-6,-7.751) 2(-5.5,-7.751) 3(-5,-7.751) 4(-4.5,-7.751) 5(-4,-7.751) 6(-3.5,-7.751) 7(-3,-7.751) 8(-2.5,-7.751) 9(-2,-7.751) 10(-1.5,-7.751) 11(-1,-7.751) 12(-0.5,-7.751) 13(0,-7.751) 14(0.5,-7.751) 15(1,-7.751) 16(1.5,-7.751) 17(2,-7.751) 18(2.5,-7.751) 19(3,-7.751) 20(3.5,-7.751) 21(4,-7.751) 22(4.5,-7.751) 23(5,-7.751) 24(5.5,-7.751) 25(6,-7.751) 51(6,7.749) 52(5.5,7.749) 53(5,7.749) 54(4.5,7.749) 55(4,7.749) 56(3.5,7.749) 57(3,7.749) 58(2.5,7.749) 59(2,7.749) 60(1.5,7.749) 61(1,7.749) 62(0.5,7.749) 63(0,7.749) 64(-0.5,7.749) 65(-1,7.749) 66(-1.5,7.749) 67(-2,7.749) 68(-2.5,7.749) 69(-3,7.749) 70(-3.5,7.749) 71(-4,7.749) 72(-4.5,7.749) 73(-5,7.749) 74(-5.5,7.749) 75(-6,7.749)
  rect 2x0.25 smd: 26(7.75,-6.001) 27(7.75,-5.501) 28(7.75,-5.001) 29(7.75,-4.501) 30(7.75,-4.001) 31(7.75,-3.501) 32(7.75,-3.001) 33(7.75,-2.501) 34(7.75,-2.001) 35(7.75,-1.501) 36(7.75,-1.001) 37(7.75,-0.501) 38(7.75,-0.001) 39(7.75,0.499) 40(7.75,0.999) 41(7.75,1.499) 42(7.75,1.999) 43(7.75,2.499) 44(7.75,2.999) 45(7.75,3.499) 46(7.75,3.999) 47(7.75,4.499) 48(7.75,4.999) 49(7.75,5.499) 50(7.75,5.999) 76(-7.75,5.999) 77(-7.75,5.499) 78(-7.75,4.999) 79(-7.75,4.499) 80(-7.75,3.999) 81(-7.75,3.499) 82(-7.75,2.999) 83(-7.75,2.499) 84(-7.75,1.999) 85(-7.75,1.499) 86(-7.75,0.999) 87(-7.75,0.499) 88(-7.75,-0.001) 89(-7.75,-0.501) 90(-7.75,-1.001) 91(-7.75,-1.501) 92(-7.75,-2.001) 93(-7.75,-2.501) 94(-7.75,-3.001) 95(-7.75,-3.501) 96(-7.75,-4.001) 97(-7.75,-4.501) 98(-7.75,-5.001) 99(-7.75,-5.501) 100(-7.75,-6.001)
  silkscreen extent -8.26,-8.03 8,8.22
VD220/16V [mil]
  rect 130x75 smd: +(95,0) -(-95,0)
  silkscreen extent -124,-124 124,124
VZH220/50V [mil]
  rect 185x100 smd: +(157.48,-0.14) -(-157.48,-0.14)
  silkscreen extent -197,-197 197,197

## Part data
B1: library part Buzzer
C0 C2_1 C5 C7 C8 C9 C10 C11 C12 C13 C33 C37 C38 C39 C101 C102 C103 CA18 CA23 CS1 LC1 LC2: library part CAP
C1 C1_1 C3_2 Cm1 Cm2 Cm3 Cm4 Cq1 Cq2 Cq3 Cq4 Cq21 Cq22 Cq23 Cq24 Cz1 Cz2 Cz3 Cz4 LC1_1 LC2_1: library part CAP, "Capacitor"
C2 C4_1 C301 C401 C501 CA101 CA601 CA1101: library part Pro82C5.TMP
C3_1: library part VZH220/50V
C6 C7_1 C8_1 CA22 CA251 CA261: library part Pro82C5.TMP_0.1uF_27
C35: library part CAP, "贴"
D1 D2 D3 D3_1 D4 D7 D10 DA03 DA05 DA06 DA12 DA14 DA15 DA18 DA20 DA21 DA22 DA23 DA26 DA27 DA29 DA31 DA31_1 DA31_2 DA32: library part DIODE
D21 D22: library part TVS, "贴片"
DAL14 DAL32 LD1 LD2 LD3 LD4 LD13 LD14 LDA31 LDX1 LDX6 LDX7 LDX14 LR1: library part LED_R
DAL15 DAL20 DAL21 DAL23 DAL29 LDX3: library part LE
DAL16 DAL18: library part LED_g, "Green"
DAL22 LD13_1 LDA05 LDX13: library part LED_y, "Yellow"
Designator25 Designator26 Designator27 Designator28: library part BNC, "BNC"
DL9 DL10 DL11 DL12 DL15 DL16 DL17 DL18: library part LED_W, "LED"
Ec01: library part ELECTROLY, "220uF/25V"
IC2: library part HT1621
IC3: library part "MC9S12HY/HA-Family 100 LQFP"
IC4 IC5: library part 2003
L1 L2 R1 R2 R3 R3_1 R3_2 R4 R6_1 R36_1 R37_1 R73 R78 RA9 RA10 RA11 RA12 RA051 RA052 RA053_1 RA131 RA132 RA133 RA142 RA151 RA152 RA153 RA161 RA162 RA163 RA181 RA182 RA183 RA201 RA202 RA203 RA211 RA212 RA213 RA231 RA232 RA233 RA271 RA272 RA273 RA281 RA282 RA283 RA284 RA284_1 RA285 RA291_1 RA291_3 RA291_4 RA292_1 RA321 RA322 RA323 RB1 RD13_1 RD14_1 RD26_1 RD26_2 RDX2 RDX3 RDX4 RDX5 RDX6 RDX7 RDX8 RDX9 RDX10 RDX11 RDX12 RDX13 RDX14 RL9_1 RL10_1 RL11_1 RL12_1 RL13 RL14 RL17 RL18: library part RES_SMD, "贴"
L1_1 R6 R18 R19 R20 R21 R22 R23 R24 R25 R26 R27 R28 R29 R30 R31 R32 R33 R34 R35 R36 R37 R38 RA141 RA143 RA291 RA292 RA293 RA294 RDX1 RL1 RL2 RL3 RL4 RL5 RL6 RL7 RL8 RL9 RL10 RL11 RL12 RS1: library part R
LCan1 LCan2: library part INDUCTOR
LD14_1 LDA03: library part LED_G, "Green"
LD26: library part Component_1
LDX2 LDX4 LDX5 LDX9 LDX11: library part LED_Y, "Yellow"
LDX10 LDX12: library part LED_r
M1 M2 M3 M4: library part JIX1N1
P4: "Port"
Q3: library part NPNN
Q11 QA28 QA29 QA29_1 QX1_1 QX2_1 QX3_1 QXF_1: library part NPN
QF1: library part "MOSFET P"
R57 R58 R59 R401 R402 R403 R505 R1301 R1302 R1303 R1304 RA221 RA222 RA223 RA601 RA602 RA603 RA604 RA1102 RA1103 RA1104 RA1201 RA1202 RA1203 RA1204 Rf4 RT131 RT141 RX1_1 RX1_2 RX2_1 RX2_2 RX3_1 RX3_2: library part RES2
R301 R302: library part ZS.S01_
R303: library part ZB314-0D.S
RA251 RA261: library part ZB314-0D.S01_2.2k_1
Rm1 Rm2 Rq1 Rq2 Rq21 Rq22 Rz1 Rz2: library part RES0603
U3: "CAN Interface"
U11: library part Component_1_1

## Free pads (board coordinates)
  round 39.37 smd far side: 43(9551,10538) 43(10058.87,10526.94) 43(12388.87,9977.94) 43(12441.87,9946.94) 43(12574,9914)

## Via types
v1: diameter 23.62, hole 11.81, Top Layer to Bottom Layer, 642 vias

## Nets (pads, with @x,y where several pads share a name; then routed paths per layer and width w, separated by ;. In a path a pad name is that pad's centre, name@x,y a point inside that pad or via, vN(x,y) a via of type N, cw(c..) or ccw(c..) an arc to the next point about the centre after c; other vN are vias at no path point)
+5V: C3_2.1 C4.+ C5.2 C7.2 C8.2 C9.2 C12.2 C13.2 C33.1 C101.2 C102.2 C103.2 Ec02.+ IC2.16 IC2.17 IC3.7 IC3.17 IC3.62 IC3.69 IC3.89 IC3.92 P4.6 R6.2 R57.2 R59.2 RB1.2 RS1.2 U1_2.1 U3.3 | length 14607
  Top Layer w9.8: v1(12482,9745) v1@12484,9745 ; IC2.16@13250.97,8440.99 13250.97,8355.03 13260,8346 13264,8350 13275.97,8361.97 IC2.17@13275.97,8440.99 13275.97,8482.35
  Top Layer w15: v1(8167,8698) 8167,9085 8349,9267 v1(8349,9423)
  Top Layer w20: C7.2@13264,8346 C7.2@13267,8343
  Top Layer w30: v1@12647,10721 12647,9970 12484,9807 12484,9745 12484,9691.04 P4.6@12543.64,9631.4 12504.4,9631.4 12475,9602 12475,9492 12515,9452 12934,9452 13085.5,9300.5 13225,9161 v1(13225,8938) ; 13261,8503 13484,8726 v1(13484,8939) ; C7.2@13264,8346 C7.2@13264,8350 ; v1(13421,9371) v1(13421,9712) 13421,10157 v1(13515,10251)
  Bottom Layer w9.8: C33.1@12425,9733 12437,9745 v1(12482,9745) ; P4.6@12543.64,9631.4 12595,9682.76 RS1.2@12595,9732 ; v1(12648,10721) 12658,10731 13097,10731 13156,10672 C102.2@13156,10660 ; C5.2@12968,9548 12968.36,9548 13034,9613.64 ; 13036.26,9615.89 IC3.17@13036.26,9917.85 ; IC3.62@13095.31,10528.09 13095.31,10590.31 13156,10651 C102.2@13156,10660 ; IC3.7@13233.11,9917.85 13233.11,9828.64 13307.75,9754 13332,9754 13371,9715 C9.2@13371,9711 13420,9711 v1(13421,9712) ; IC3.69@13233.47,10528.45 IC3.69@13233.11,10528.09 13233.11,10655.89 13228,10661 13227,10660 C102.2@13156,10660 ; IC3.92@13420.12,10144.23 13548.86,10144.23 13637,10232.36 RB1.2@13637,10247 13637,10255 13601.79,10290.21 13552.02,10290.21 13513.9,10252.1 13465.09,10203.28 IC3.89@13420.12,10203.28
  Bottom Layer w15: R59.2@8288,9418 8293,9423 v1(8349,9423) ; U3.3@12327,9717 12409,9717 C33.1@12425,9733 ; RS1.2@12592,9738 C8.2@12592,9814.24
  Bottom Layer w30: R57.2@7859,9135 U1_2.1@7859,9309 ; U1_2.1@7864,9315 U1_2.1@7867,9315 ; C4.+@12928,9138 12928,9189 v1(13062,9323) 13110,9371 v1(13421,9371) ; v1(12950,9439) 12968,9457 C5.2@12968,9548 ; C4.+@12955,9177 13137,9359 ; v1(13225,8938) 13483,8938 v1(13484,8939) 13559,8939 R6.2@13560,8938 ; v1@13513.9,10252.1 v1(13515,10251)
  Bottom Layer w40: R57.2@7857,9133 R57.2@7857,9130 7857,8980 8139,8698 v1(8167,8698) 9643,8698 10108,9163 12903,9163
  other v1: 13085,9300
+12V: DAL22.1 LD13_1.1 LD14_1.1 LD26.2 LD26.3 LDX1.1 LDX2.1 LDX3.1 LDX4.1 LDX5.1 LDX6.1 LDX7.1 LDX9.1 LDX10.1 LDX11.1 LDX12.1 LDX13.1 LDX14.1 QF1.D R3.1 R401.2 R1301.2 R1302.2 R1303.2 R1304.2 RA601.1 RA1201.2 | length 15326.4
  Top Layer w15: LD26.2@8419,10161.09 v1(8469.09,10161.09) ; DAL22.1@8713,10318 8794,10237 v1(8794,10004) ; v1(9104,9832) 9104,9424 LDX6.1@9194,9334 ; v1(11612,10239) 11649,10202 LDX14.1@11678,10202 ; LDX5.1@11928,10546 11948,10526 v1(11948,10231) ; LDX3.1@12178.63,10991.39 12178.63,10915.37 v1(12180,10914) ; v1(14435,10934) 14436,10935 v1(14436,11268) ; LDX11.1@14627,10314 14644,10331 v1(14644,10931)
  Top Layer w20: LD13_1.1@8136.37,9861.61 8285.14,10010.38 LD26.3@8285.14,10104 8318,10104 8375.09,10161.09 LD26.2@8419,10161.09 ; DAL22.1@8699,10332 DAL22.1@8713,10318 ; v1(11161,10236) 11161,10169 LDX13.1@11164,10166 ; LDX9.1@11161,10992 LDX9.1@11161,10995 ; LDX10.1@14149,9466 14090,9525 14090,9725 14148,9783 14148,9805 v1(14197,9854) ; v1(14525,10004) 14525,10212 LDX11.1@14627,10314
  Top Layer w30: v1(9812,9832) v1(9812,10197) ; v1(10536,11019) 10562,11019 10636,10945 LDX4.1@10646,10945 ; v1(10776,10234) 10776,10513 10901,10638 v1(10901,10888) ; v1(11056,10889) 11159,10992 LDX9.1@11161,10992 ; v1(11415,10237) 11417,10239 LDX12.1@11417,10539 11672,10794 v1(11672,10914) LD14_1.1@11672,11005 ; v1(12124,10236) 12182.39,10177.61 LDX1.1@12184.37,10177.61
  Bottom Layer w15: v1(8469.09,10161.09) 8582.17,10048 8748,10048 8964,9832 v1(9104,9832) v1(9812,9832) ; v1@11612,10236 v1(11612,10239) ; v1(11672,10914) v1(12180,10914) 13104,10914 13458,11268 v1(14436,11268) ; v1(11948,10231) v1@11948,10236 ; v1(14435,10934) 14641,10934 v1(14644,10931)
  Bottom Layer w20: v1(14197,9854) 14347,10004 v1(14525,10004)
  Bottom Layer w30: R3.1@9426,10446 9426,10234 9463,10197 v1(9812,10197) ; R3.1@9432.62,10418 QF1.D@9532,10418 ; 9435,10362 9437.62,10364.62 ; v1@9809,10194 v1(9812,10197) ; RA601.1@9828,10129 9828,10199 ; R1304.2@10308,10946.39 R1303.2@10417,10946.39 R1302.2@10531,10946.39 ; v1(10536,11019) 10536,10951.39 R1302.2@10531,10946.39 ; v1(10776,10234) v1@10776,10236 ; RA1201.2@10815,10715 10847,10747 10847,10885 10851,10889 ; v1(10901,10888) v1@10901,10889 ; R401.2@11157,10859 11127,10889 v1(11056,10889) v1@10901,10889 ; v1(11415,10237) v1@11415,10236 ; v1(12124,10236) 11948,10236 11612,10236 v1@11415,10236 ; v1(9812,10197) 9851,10236 v1@10776,10236 ; R1302.2@10531,10946.39 R1301.2@10647,10946.39 10704.39,10889 10851,10889 ; v1@10776,10236 v1(11161,10236) v1@11415,10236 ; 10851,10889 v1@10901,10889
+12V_OUT: P1.4 R3.2 | length 887.5
  Bottom Layer w20: P1.4@8582.79,10866.69 8920.74,10528.74 9205.26,10528.74 9288,10446 R3.2@9296,10446
+BATTERY: L1.2 LC1.2 P1.2 | length 491.3
  Bottom Layer w40: L1.2@8158,10520 8179,10541 LC1.2@8267,10541 8382.79,10656.79 P1.2@8382.79,10866.69
+IG: L2.2 LC2.1 P1.1 | length 578.1
  Bottom Layer w40: L2.2@7823,10771 LC2.1@7823,10871 ; 7824,10820 8236.09,10820 P1.1@8282.79,10866.69
ABS+: P1.29 RA291.1 RA293.1 | length 3495.7
  Top Layer w15: P1.29@9482.79,10966.69 9531,10918.48 9531,10851 9536.26,10845.74 9536.26,10844.45 9583.7,10797 v1(9629,10797) ; v1(10014,10767) 10048,10733 v1(10048,10655) ; v1(12081,10547) v1(12081,11010)
  Bottom Layer w15: v1(9629,10797) 9659,10767 v1(10014,10767) ; v1(10048,10655) 10262,10655 10377,10540 12074,10540 v1(12081,10547) ; v1(12081,11010) 12081,11080 RA293.1@12075,11086 12164,11086 RA291.1@12165,11087
BKGD: IC3.90 P4.1 RB1.1 | length 1753.4
  Top Layer w15: P4.1@12743,9530 13003,9530 v1(13118,9415) ; v1(13480,9420) 13478.5,9420 13478.5,10149.5 v1(13524,10195)
  Bottom Layer w9.8: IC3.90@13420.12,10183.6 13521.6,10183.6 RB1.1@13571,10233
  Bottom Layer w15: v1(13118,9415) 13123,9420 v1(13480,9420)
BOX-: DA27.2 P1.27 | length 278.5
  Top Layer w15: P1.27@9282.79,10966.69 9332,10917.48 9332,10833 DA27.2@9420,10745
BRAKE+: P1.28 RA281.1 RA283.1 | length 4584.4
  Top Layer w15: v1(7280,11060) 7272.5,11052.5 7272.5,9386.5 7376,9283 7376,9023 RA283.1@7382,9017 ; RA283.1@7378,9024 7382,9020 RA283.1@7382,9017 ; RA281.1@7382,8937 RA283.1@7382,9017 ; v1(9382.57,11207) 9382.79,11207.21 P1.28@9382.79,10966.69
  Bottom Layer w15: v1(7280,11060) 7283.5,11063.5 8841.53,11063.5 8843.22,11065.19 8967.19,11065.19 9109,11207 v1(9382.57,11207)
BRAKE-: DA31_1.2 P1.31 | length 4532
  Top Layer w15: v1(7240,10985) 7240,9297 DA31_1.2@7289,9248 ; v1(9629,11229) 9682.79,11175.21 P1.31@9682.79,10966.69
  Bottom Layer w15: v1(7240,10985) 7245.74,10985 7299.74,11039 8851.67,11039 8853.37,11040.69 8978.69,11040.69 9112,11174 9574,11174 v1(9629,11229)
CANH: C37.1 C39.2 D22.E LCan2.2 P1.11 pad.43@10058.87,10526.94 | length 3438.1
  Top Layer w12: v1(11988,10418) 11989,10417 v1(11989,10008)
  Bottom Layer w12: P1.11@9282.79,10866.69 9610.48,10539 9885.62,10539 9897.68,10526.94 pad.43@10058.87,10526.94 10114.06,10526.94 10219.69,10421.31 11984.69,10421.31 v1(11988,10418) ; v1(11989,10008) 11989,9956 LCan2.2@11992,9953 ; LCan2.2@11993,9954 LCan2.2@11992,9953 ; C37.1@12071,9953 LCan2.2@11992,9953
CANL: C38.2 C39.1 D21.B LCan1.2 P1.10 pad.43@9551,10538 | length 3451.3
  Top Layer w12: v1(11915,10394) 11916,10393 v1(11916,10009)
  Bottom Layer w12: P1.10@9182.79,10866.69 9272.74,10776.74 9273.24,10777.24 9319.76,10777.24 9629,10468 C39.1@9638,10468 9678,10428 D21.B@9737.62,10428 9771.62,10394 v1(11915,10394) ; C38.2@11832,9952 LCan1.2@11910,9952 11916,9958 v1(11916,10009)
CHARGE-: D7.2 P1.24 | length 118.5
  Top Layer w30: D7.2@8980,11084 8982.79,11081.21 P1.24@8982.79,10966.69
COM0: IC2.24 U11.17 | length 1257.1
  Top Layer w9.8: 12670,7881.82 12681.29,7881.82 13005.97,8206.5 13300.68,8206.5 13450.97,8356.79 IC2.24@13450.97,8440.99
  Top Layer w30: U11.17@12474.78,7881.82 12670,7881.82
COM1: IC2.23 U11.16 | length 1330.8
  Top Layer w9.8: 12426.96,7934 12438.76,7945.8 12717.98,7945.8 12997.98,8225.8 13292.68,8225.8 13425.97,8359.09 IC2.23@13425.97,8440.99
  Top Layer w30: U11.16@12374.78,7881.82 12426.96,7934
COM2: IC2.22 U11.15 | length 1507.5
  Top Layer w9.8: U11.15@12274.78,7881.82 12358.06,7965.1 12709.98,7965.1 12989.98,8245.1 13284.69,8245.1 13400.97,8361.38 IC2.22@13400.97,8440.99
  Top Layer w30: U11.15@12274.78,7881.82 12282.82,7881.82 12350,7949
COM3: IC2.21 U11.14 | length 1478.1
  Top Layer w9.8: 12264.96,7972 12277.36,7984.4 12701.99,7984.4 12981.99,8264.4 13276.69,8264.4 13375.97,8363.68 IC2.21@13375.97,8440.99
  Top Layer w30: U11.14@12174.78,7881.82 12264.96,7972
CRXD: IC3.27 pad.43@12574,9914 U3.4 | length 695.7
  Bottom Layer w9.8: U3.4@12327,9667 12441.07,9667 12512.5,9738.43 12512.5,9852.5 pad.43@12571,9911 ; pad.43@12574,9914 pad.43@12571,9911 ; IC3.27@12809.88,10006.43 12664.43,10006.43 12571,9913 pad.43@12571,9911
CSTB: IC3.29 pad.43@12388.87,9977.94 U3.8 | length 797.7
  Bottom Layer w9.8: U3.8@12107,9817 12227.92,9817 pad.43@12388.87,9977.94 12456.72,10045.8 IC3.29@12809.88,10045.8
CTXD: IC3.28 pad.43@12441.87,9946.94 U3.1 | length 588.6
  Bottom Layer w9.8: U3.1@12327,9817 12327,9849.66 12407,9929.66 12503.45,10026.12 IC3.28@12809.88,10026.12
DOOR-: DA14.2 P1.14 | length 6005.8
  Top Layer w15: P1.14@9582.79,10866.69 9632,10915.91 v1(9632,11174) ; DA14.2@14859,11154 v1(14859,11344)
  Bottom Layer w15: 10116,11381 10937.73,11381 11010.73,11454 11484.37,11454 11552.37,11522 12989,11522 13218.5,11292.5 14089.44,11292.5 14139.94,11343 14859,11343 v1(14859,11344)
  Bottom Layer w20: v1(9632,11174) 9701,11243 9978,11243 10116,11381
"EXHAUST BRAKE+": DA22.1 P1.22 | length 1472.2
  Bottom Layer w15: P1.22@8782.79,10966.69 8830.59,11014.5 8861.82,11014.5 8863.51,11016.19 8988.84,11016.19 9114.15,11141.5 9673.8,11141.5 9740.15,11207.85 10048.85,11207.85 DA22.1@10124,11283
"FRONT FOG+": DA21.1 P1.21 | length 299.1
  Top Layer w15: DA21.1@8618,11239 8618,11235 8682.79,11170.21 P1.21@8682.79,10966.69
FUEL: P1.13 R505.2 R1301.1 R1302.1 R1303.1 R1304.1 | length 1377.9
  Bottom Layer w30: P1.13@9482.79,10866.69 9620.48,10729 10241,10729 R1304.1@10316,10804 ; R1304.1@10308,10816.39 R1303.1@10417,10816.39 R1302.1@10531,10816.39 R1301.1@10647,10816.39 10762.61,10816.39 R505.2@10764,10815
